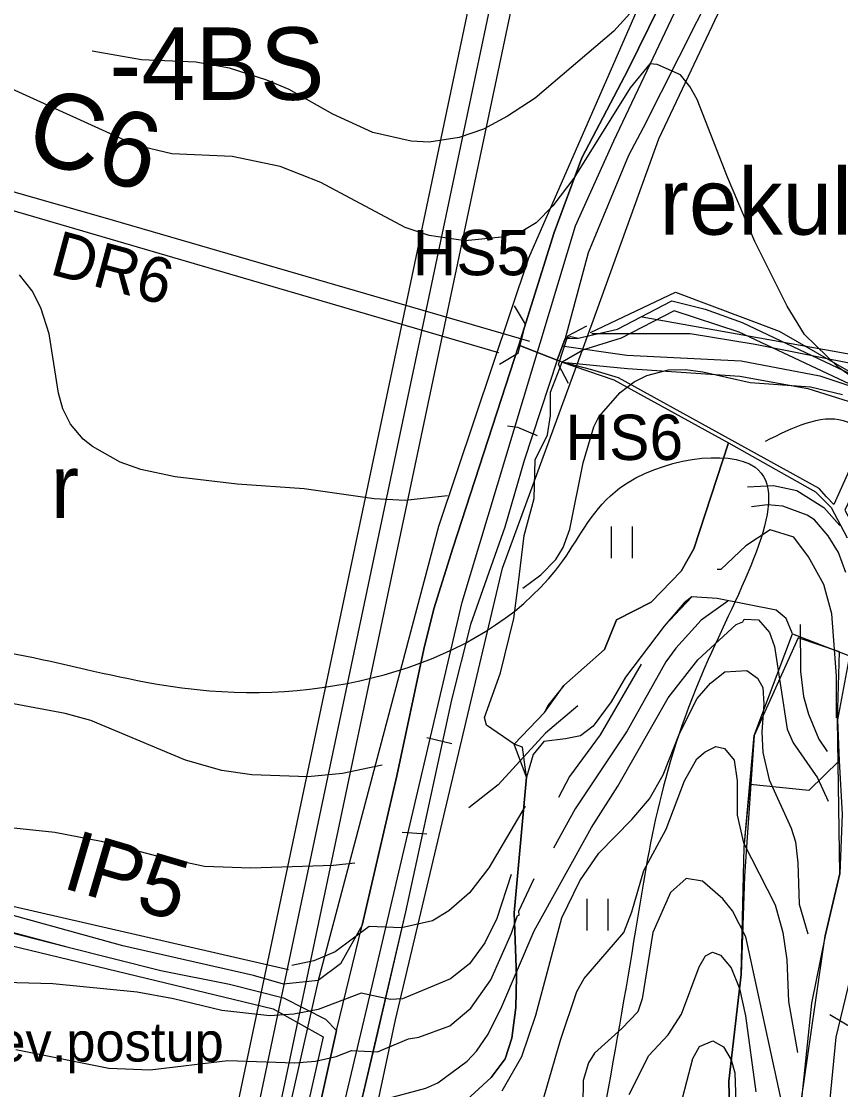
# Model space of a CAD drawing. Extents: x -684583 to -680383, y -1157874 to -1154904.
# Drawn here: x -683067.1 to -682795.6, y -1156658.6 to -1156304.8 of the extents above; entities that cross this region are included whole.
import ezdxf

# ---------------------------------------------------------------- set-up
doc = ezdxf.new("R2010")
doc.units = 0
for name, color, linetype in [('01_DOPRAVA', 7, 'Continuous'), ('01_VRSTEVNICE', 7, 'Continuous'), ('02_KULTURY NÁVRH', 7, 'Continuous'), ('02_KULTURY STAV', 7, 'Continuous'), ('03_PC_NÁVRH', 7, 'Continuous'), ('03_PC_OBJEKTY_NÁVRH', 7, 'Continuous'), ('03_PC_OBJEKTY_STAV', 7, 'Continuous'), ('03_PC_POPIS_NÁVRH', 7, 'Continuous'), ('04_ZPF_OP_ORGAN', 7, 'Continuous'), ('06_BIOGEOGRAFIE', 7, 'Continuous'), ('06_REVITALIZACE', 7, 'Continuous'), ('06_ÚSES_IP', 7, 'Continuous'), ('07_ELEKTRO', 7, 'Continuous'), ('07_OCH_P A POPISY TI', 7, 'Continuous')]:
    doc.layers.add(name, color=color, linetype=linetype)

msp = doc.modelspace()

# ---------------------------------------------------------------- linework, layer by layer
at = {"layer": '01_DOPRAVA'}
msp.add_lwpolyline([(-683054.51, -1157758.92), (-683045.66, -1157702.14), (-683033.32, -1157625.99), (-683033.32, -1157571.3), (-683045.07, -1157508.09), (-683105.62, -1157372.25), (-683148.82, -1157294.04), (-683163.81, -1157254.05), (-683168.81, -1157196.71), (-683165.28, -1157159.67), (-683135.89, -1157075.28), (-683079.46, -1156981.49), (-683035.96, -1156902.98), (-682993.94, -1156817.72), (-682972.78, -1156716.87), (-682952.5, -1156631.31), (-682921.05, -1156497.23), (-682883.43, -1156372.57), (-682870.79, -1156344.34), (-682802.61, -1156200.56), (-682782.62, -1156147.93)], dxfattribs=at)
at = {"layer": '01_VRSTEVNICE'}
for points in [[(-682859.06, -1156295.03), (-682870.76, -1156308.01), (-682896.86, -1156330.26), (-682905.99, -1156336.25), (-682913.98, -1156340.53), (-682921.97, -1156343.24), (-682931.95, -1156344.81), (-682937.94, -1156344.53), (-682950.64, -1156341.67), (-682963.91, -1156335.54), (-682978.31, -1156327.41), (-682985.73, -1156324.27), (-682998.14, -1156320.28), (-683009.27, -1156318.28), (-683027.24, -1156317.57), (-683043.64, -1156314.71)], [(-682788.45, -1156424.98), (-682796.3, -1156419.41), (-682807.57, -1156408.57), (-682813.27, -1156399.16), (-682823.97, -1156377.76), (-682833.1, -1156356.37), (-682843.09, -1156330.69), (-682845.51, -1156326.41), (-682848.65, -1156322.56), (-682856.35, -1156319.14), (-682858.78, -1156318.85), (-682865.34, -1156326.84), (-682884.02, -1156356.79), (-682891.01, -1156365.92), (-682896.43, -1156371.49), (-682900.86, -1156374.2), (-682907.99, -1156376.34), (-682919.97, -1156377.48), (-682931.95, -1156375.77), (-682939.94, -1156373.06), (-682967.9, -1156358.22), (-682981.31, -1156352.94), (-682997.28, -1156349.52), (-683017.25, -1156348.66), (-683029.24, -1156345.81), (-683070.32, -1156327.12)], [(-682925.82, -1156461.92), (-682939.94, -1156463.49), (-682950.21, -1156462.92), (-682973.32, -1156459.64), (-682995.57, -1156458.07), (-683016.11, -1156455.65), (-683027.52, -1156453.22), (-683034.37, -1156450.8), (-683043.5, -1156445.66), (-683046.64, -1156443.24), (-683050.78, -1156438.24), (-683053.34, -1156433.11), (-683054.77, -1156427.97), (-683057.91, -1156408.29), (-683060.62, -1156399.73), (-683063.47, -1156394.03), (-683067.75, -1156388.75)], [(-682900.86, -1156492.5), (-682894.99, -1156488.18), (-682890.01, -1156483.03), (-682887.59, -1156479.04), (-682885.31, -1156473.05), (-682880.89, -1156451.08), (-682877.32, -1156439.1), (-682875.75, -1156435.82), (-682868.62, -1156427.69), (-682864.05, -1156424.26), (-682859.78, -1156422.13), (-682852.64, -1156420.27), (-682846.94, -1156420.13), (-682841.23, -1156420.84), (-682825.54, -1156424.41), (-682805.57, -1156425.83), (-682795.01, -1156428.4)], [(-682905.95, -1156438.78), (-682902.71, -1156439.24), (-682896.15, -1156441.95)], [(-682826.41, -1156458.93), (-682817.87, -1156458.52), (-682810.05, -1156460.17), (-682801.15, -1156465.78), (-682795.87, -1156471.77)], [(-682793.87, -1156487.31), (-682796.3, -1156480.75), (-682799.72, -1156475.19), (-682804.29, -1156469.91), (-682806.71, -1156468.34), (-682814.7, -1156465.35), (-682819.83, -1156464.92), (-682825.11, -1156465.63)], [(-682796.95, -1156535.47), (-682796.95, -1156521.68), (-682798.5, -1156501), (-682801.15, -1156491.31), (-682806.28, -1156482.18), (-682811.13, -1156475.62), (-682818.98, -1156473.19), (-682826.97, -1156478.47), (-682835.24, -1156486.31), (-682836.52, -1156486.31)], [(-682832.96, -1156496.87), (-682841.8, -1156503.15), (-682850.22, -1156512.42), (-682853.5, -1156516.98), (-682866.34, -1156539.81), (-682883.6, -1156565.62), (-682890.73, -1156578.61)], [(-682947.07, -1156661.91), (-682933.09, -1156658.2), (-682929.1, -1156656.35), (-682919.4, -1156649.21), (-682916.26, -1156645.93), (-682912.41, -1156640.23), (-682907.85, -1156631.1), (-682897.15, -1156605.99), (-682878.18, -1156571.76), (-682869.47, -1156558.07), (-682852.79, -1156528.82), (-682842.94, -1156516.27), (-682830.25, -1156504.57), (-682827.96, -1156503.72), (-682827.54, -1156502.86), (-682822.83, -1156503), (-682819.12, -1156507.28), (-682817.55, -1156511.85)], [(-682808.99, -1156504.57), (-682808.85, -1156520.12), (-682807.85, -1156528.4), (-682806.28, -1156534.24), (-682802.86, -1156542.52), (-682800.01, -1156546.65)], [(-682817.55, -1156511.85), (-682813.27, -1156539.24), (-682811.28, -1156543.8), (-682803.28, -1156555.41), (-682799.72, -1156563.06)], [(-682861.73, -1156517.71), (-682875.31, -1156541.17), (-682885.45, -1156554.93), (-682889.13, -1156561.83)], [(-682907.7, -1156659.06), (-682901.28, -1156647.65), (-682896.58, -1156633.95), (-682888.02, -1156601.71), (-682882.03, -1156589.45), (-682875.75, -1156580.32), (-682864.77, -1156569.19), (-682858.92, -1156562.34), (-682854.35, -1156554.36), (-682848.93, -1156540.66), (-682843.09, -1156529.11), (-682838.66, -1156523.97), (-682833.96, -1156520.26), (-682826.68, -1156519.84), (-682823.12, -1156522.4), (-682821.4, -1156525.4), (-682820.98, -1156530.96), (-682821.69, -1156540.09), (-682821.4, -1156546.94), (-682819.26, -1156556.07), (-682811.99, -1156572.04), (-682810.56, -1156576.61), (-682809.71, -1156583.46)], [(-682947.5, -1156551.22), (-682960.62, -1156553.93), (-682972.18, -1156555.07), (-682990.72, -1156554.36), (-683000.71, -1156552.93), (-683012.69, -1156549.51), (-683044.07, -1156536.38), (-683052.63, -1156534.1), (-683069.75, -1156530.82)], [(-682882.62, -1156531.49), (-682893.44, -1156540.52), (-682909.13, -1156557.64), (-682918.83, -1156565.34)], [(-682924.39, -1156544.09), (-682932.67, -1156542.09)], [(-682895.72, -1156667.33), (-682888.45, -1156642.22), (-682883.03, -1156626.11), (-682880.6, -1156621.83), (-682867.48, -1156606.56), (-682864.77, -1156599.72), (-682860.77, -1156586.02), (-682853.36, -1156572.33), (-682847.36, -1156556.35), (-682843.23, -1156549.08), (-682840.52, -1156546.8), (-682836.95, -1156544.94), (-682834.1, -1156545.65), (-682830.82, -1156549.51), (-682829.82, -1156556.35), (-682829.82, -1156567.76), (-682827.82, -1156576.89), (-682817.27, -1156597.43), (-682814.7, -1156606.56), (-682813.42, -1156615.69), (-682812.84, -1156629.39), (-682809.85, -1156646.36)], [(-682900.08, -1156564.75), (-682912.12, -1156585.17), (-682918.54, -1156593.44), (-682925.39, -1156599.43), (-682930.81, -1156602.71), (-682941.08, -1156604.99), (-682951.78, -1156604.57), (-682963.05, -1156612.98), (-682970.18, -1156615.98), (-682977.46, -1156617.55)], [(-683091.71, -1156569.62), (-683056.05, -1156573.33), (-683040.65, -1156576.32), (-683021.82, -1156581.32), (-683006.41, -1156584.6), (-682991.01, -1156585.17), (-682963.62, -1156584.31), (-682956.63, -1156583.46)], [(-682932.67, -1156574.04), (-682940.94, -1156573.47)], [(-682809.71, -1156583.46), (-682809.28, -1156597.15), (-682806.43, -1156606.99)], [(-682904.77, -1156587.35), (-682909.56, -1156602), (-682913.55, -1156609.99), (-682918.54, -1156616.98), (-682924.82, -1156621.97), (-682940.8, -1156628.53), (-682944.79, -1156628.82), (-682954.49, -1156626.68), (-682968.75, -1156632.1), (-682976.74, -1156633.67), (-682984.73, -1156634.24), (-683000.71, -1156632.38), (-683016.68, -1156628.53), (-683028.67, -1156626.39), (-683056.62, -1156623.54), (-683072.6, -1156623.11)], [(-683068.89, -1156645.36), (-683038.08, -1156651.5), (-683024.39, -1156652.07), (-682998.71, -1156648.93), (-682976.46, -1156649.78), (-682969.61, -1156649.21), (-682962.76, -1156647.65), (-682957.63, -1156645.65), (-682949.07, -1156646.08), (-682938.8, -1156641.8), (-682935.38, -1156641.23), (-682925.11, -1156637.52), (-682918.12, -1156631.67), (-682911.55, -1156622.25), (-682904.71, -1156606.85), (-682902.71, -1156601), (-682902.14, -1156600.86), (-682902.28, -1156599.5), (-682897.15, -1156588.73)], [(-682814.94, -1156663.44), (-682826.97, -1156607.99), (-682831.39, -1156599.43), (-682834.67, -1156595.44), (-682841.37, -1156589.59), (-682846.79, -1156588.73), (-682851.93, -1156593.3), (-682857.78, -1156606.56), (-682861.34, -1156628.53), (-682862.77, -1156632.81), (-682868.05, -1156638.37), (-682877.18, -1156646.5), (-682879.17, -1156649.78), (-682880.89, -1156655.63), (-682881.17, -1156671.89)], [(-682865.62, -1156660.2), (-682859.2, -1156647.36), (-682852.79, -1156640.51), (-682848.36, -1156633.67), (-682842.51, -1156617.98), (-682840.38, -1156614.27), (-682838.09, -1156613.13), (-682835.38, -1156614.12), (-682831.82, -1156618.26), (-682829.11, -1156625.11), (-682827.11, -1156634.24), (-682823.69, -1156659.34)], [(-682799.14, -1156633.78), (-682786.88, -1156641.08), (-682763.92, -1156656.63), (-682743.38, -1156668.04), (-682727.4, -1156674.6), (-682711.42, -1156679.74), (-682687.46, -1156686.02), (-682675.05, -1156691.01), (-682666.35, -1156697.29), (-682664.21, -1156699.57), (-682660.07, -1156706.41), (-682658.36, -1156710.98), (-682656.65, -1156720.11), (-682657.51, -1156744.93), (-682655.51, -1156761.9), (-682655.51, -1156767.47), (-682657.51, -1156777.74), (-682660.5, -1156786.3), (-682661.93, -1156792.86), (-682662.88, -1156799.77), (-682662.11, -1156829.16)], [(-682849.93, -1156669.04), (-682844.51, -1156648.36), (-682842.37, -1156644.36), (-682837.95, -1156642.51), (-682834.38, -1156644.51), (-682831.82, -1156648.79), (-682830.68, -1156653.07), (-682830.25, -1156665.9)]]:
    msp.add_lwpolyline(points, dxfattribs=at)
at = {"layer": '02_KULTURY NÁVRH'}
for points in [[(-682887.91, -1156417.72), (-682866.23, -1156419.79), (-682828.98, -1156422.33), (-682806.49, -1156426.37), (-682783.26, -1156433.67), (-682787.89, -1156443.08), (-682788.73, -1156444.69), (-682797.87, -1156464.81), (-682800.21, -1156462.31), (-682802.73, -1156459.5), (-682869.24, -1156422.91), (-682878.07, -1156420.23)], [(-682811.55, -1156507.67), (-682792.62, -1156514.96), (-682796.58, -1156536.16), (-682796.03, -1156549.68), (-682806.13, -1156559.58), (-682825.6, -1156557.59), (-682824.2, -1156541.34)]]:
    msp.add_lwpolyline(points, close=True, dxfattribs=at)
at = {"layer": '02_KULTURY STAV'}
for points in [[(-682848.78, -1156285.62), (-682866.04, -1156320.76), (-682881.3, -1156350.03), (-682890.5, -1156374.69), (-682902.2, -1156412.07), (-682924.11, -1156479.25), (-682930.39, -1156499.36), (-682933.67, -1156512.75), (-682942.64, -1156554.75), (-682954.15, -1156604.14), (-682961.33, -1156617), (-682968.71, -1156622.54), (-682980.17, -1156623.7), (-682990.2, -1156620.86), (-683033.47, -1156611), (-683082.29, -1156597.58)], [(-682837.34, -1156293.13), (-682860.97, -1156340.11), (-682865.88, -1156349.21), (-682879.26, -1156381.53), (-682886.9, -1156409.8), (-682889.47, -1156417.03), (-682902.2, -1156412.07), (-682890.5, -1156374.69), (-682881.3, -1156350.03), (-682866.04, -1156320.76), (-682848.78, -1156285.62)], [(-682837.34, -1156293.13), (-682860.97, -1156340.11), (-682865.88, -1156349.21), (-682879.26, -1156381.53), (-682886.9, -1156409.8), (-682882.56, -1156409.71), (-682869.55, -1156406.81), (-682851.47, -1156397.34), (-682840.47, -1156400.15), (-682828.26, -1156404.5), (-682752.66, -1156440.28), (-682665.48, -1156481.67), (-682644.77, -1156490.96), (-682634.17, -1156493.17), (-682633.78, -1156490.12), (-682629.07, -1156473.67), (-682624.47, -1156460.14), (-682619.39, -1156445.85), (-682614.21, -1156430.78), (-682608.85, -1156415.21), (-682596.72, -1156380.07), (-682557.32, -1156288.22)], [(-682754.25, -1156442.99), (-682829.25, -1156407.8), (-682850.76, -1156400.72), (-682868.28, -1156409.71), (-682880.84, -1156413.58), (-682887.91, -1156417.72), (-682870.7, -1156423.51), (-682832.78, -1156444.43), (-682803.95, -1156460.65), (-682798.7, -1156465.79), (-682793.43, -1156475.86)], [(-682922.2, -1156664.52), (-682911.39, -1156654.62), (-682906.77, -1156648.44), (-682904.56, -1156641.63), (-682903.21, -1156631.38), (-682903.03, -1156621.21), (-682903.76, -1156600.02), (-682899.73, -1156555.19), (-682901.04, -1156545.15), (-682903.77, -1156544.17), (-682912.98, -1156537.95), (-682913.56, -1156535.35), (-682908.35, -1156520.61), (-682903.84, -1156502.54), (-682902.5, -1156491.58), (-682900.5, -1156475.1), (-682897.2, -1156462.81), (-682896.82, -1156450.01), (-682892.68, -1156441.75), (-682891.73, -1156435.33), (-682891.71, -1156427.67), (-682887.91, -1156417.72), (-682889.47, -1156417.03), (-682900.44, -1156450.21), (-682906.88, -1156472.32), (-682912.15, -1156487.33), (-682918.22, -1156504.6), (-682924.52, -1156529.58), (-682939.75, -1156599.76), (-682962.33, -1156695.9)], [(-682832.12, -1156679.28), (-682832.61, -1156655.83), (-682828.57, -1156620.45), (-682827.59, -1156578.27), (-682825.6, -1156557.59), (-682824.2, -1156541.34), (-682811.55, -1156507.67), (-682813.64, -1156502.61), (-682816.94, -1156499.88), (-682836.55, -1156495.99), (-682844.88, -1156495.39), (-682847.39, -1156497.44), (-682854.11, -1156505.13), (-682866.83, -1156522.06), (-682871.68, -1156530.15), (-682877.57, -1156538.3), (-682881.79, -1156541.44), (-682886.74, -1156542.41), (-682893.92, -1156543.32), (-682897.52, -1156547.62), (-682899.73, -1156555.19), (-682903.77, -1156544.17), (-682893.76, -1156533.76), (-682887.33, -1156524.78), (-682873.81, -1156512.91), (-682869.89, -1156502.98), (-682858.35, -1156497.14), (-682848.45, -1156486.87), (-682844.25, -1156479.54), (-682832.78, -1156444.43), (-682803.95, -1156460.65), (-682798.7, -1156465.79), (-682793.43, -1156475.86)], [(-682871.68, -1156472.16), (-682871.68, -1156482.66)], [(-682864.68, -1156472.16), (-682864.68, -1156482.66)], [(-682832.12, -1156679.28), (-682832.61, -1156655.83), (-682828.57, -1156620.45), (-682827.59, -1156578.27), (-682824.2, -1156541.34), (-682811.55, -1156507.67), (-682813.64, -1156502.61), (-682816.94, -1156499.88), (-682836.55, -1156495.99), (-682844.88, -1156495.39), (-682854.11, -1156505.13), (-682866.83, -1156522.06), (-682871.68, -1156530.15), (-682877.57, -1156538.3), (-682881.79, -1156541.44), (-682886.74, -1156542.41), (-682893.92, -1156543.32), (-682897.52, -1156547.62), (-682899.73, -1156555.19), (-682903.76, -1156600.02), (-682903.03, -1156621.21), (-682903.21, -1156631.38), (-682904.56, -1156641.63), (-682906.77, -1156648.44), (-682911.39, -1156654.62), (-682922.2, -1156664.52)], [(-682792.62, -1156514.96), (-682796.58, -1156536.16), (-682796.03, -1156549.68), (-682795.1, -1156567.41), (-682795.87, -1156587.1), (-682800.74, -1156607.7), (-682805.25, -1156630.03), (-682808.53, -1156661.75), (-682809.42, -1156675.8), (-682811.51, -1156694.23), (-682814.12, -1156742.41), (-682814.76, -1156765.27), (-682825.52, -1156817.11), (-682826.23, -1156835.78), (-682833.65, -1156897.15), (-682841.03, -1156977.03), (-682844.53, -1157035.81), (-682845.68, -1157065.25), (-682844.82, -1157086.77), (-682850.09, -1157090.88), (-682805.97, -1157127.99), (-682750, -1157164.87)], [(-682792.62, -1156514.96), (-682796.58, -1156536.16), (-682796.03, -1156549.68), (-682795.1, -1156567.41), (-682795.87, -1156587.1), (-682800.74, -1156607.7), (-682805.25, -1156630.03), (-682808.53, -1156661.75)], [(-682879.74, -1156595.4), (-682879.74, -1156605.9)], [(-682872.74, -1156595.4), (-682872.74, -1156605.9)]]:
    msp.add_lwpolyline(points, dxfattribs=at)
for points in [[(-682889.47, -1156417.03), (-682886.9, -1156409.8), (-682885.02, -1156409.17), (-682882.56, -1156409.71), (-682869.55, -1156406.81), (-682851.47, -1156397.34), (-682840.47, -1156400.15), (-682828.26, -1156404.5), (-682752.66, -1156440.28), (-682665.48, -1156481.67), (-682644.77, -1156490.96), (-682635.67, -1156493), (-682634.17, -1156493.17), (-682635.01, -1156500.02), (-682667.07, -1156484.3), (-682754.25, -1156442.99), (-682829.25, -1156407.8), (-682850.76, -1156400.72), (-682868.28, -1156409.71), (-682880.84, -1156413.58), (-682887.91, -1156417.72)], [(-682976.5, -1156701.12), (-682962.69, -1156639.04), (-682954.15, -1156604.14), (-682942.64, -1156554.75), (-682933.67, -1156512.75), (-682930.39, -1156499.36), (-682924.11, -1156479.25), (-682902.2, -1156412.07), (-682889.47, -1156417.03), (-682900.44, -1156450.21), (-682906.88, -1156472.32), (-682918.22, -1156504.6), (-682924.52, -1156529.58), (-682939.75, -1156599.76), (-682949.64, -1156642.25), (-682962.33, -1156695.9)], [(-682887.91, -1156417.72), (-682870.7, -1156423.51), (-682832.78, -1156444.43), (-682844.25, -1156479.54), (-682848.45, -1156486.87), (-682858.35, -1156497.14), (-682869.89, -1156502.98), (-682873.81, -1156512.91), (-682887.33, -1156524.78), (-682892.59, -1156531.36), (-682893.76, -1156533.76), (-682903.77, -1156544.17), (-682912.98, -1156537.95), (-682913.56, -1156535.35), (-682908.35, -1156520.61), (-682903.84, -1156502.54), (-682902.5, -1156491.58), (-682900.5, -1156475.1), (-682897.2, -1156462.81), (-682896.82, -1156450.01), (-682892.68, -1156441.75), (-682891.73, -1156435.33), (-682891.71, -1156427.67)], [(-683092.79, -1156585.88), (-683084.93, -1156572.48), (-683093.79, -1156577.44), (-683104.92, -1156586.73), (-683111.36, -1156596.26), (-683088.76, -1156601.48), (-683052.03, -1156611.32), (-683020.92, -1156619.13), (-682998.1, -1156623.73), (-682980.21, -1156628.28), (-682966.28, -1156635.31), (-682962.69, -1156639.04), (-682954.15, -1156604.14), (-682961.33, -1156617), (-682968.71, -1156622.54), (-682980.17, -1156623.7), (-682990.2, -1156620.86), (-683033.47, -1156611), (-683082.29, -1156597.58), (-683095.01, -1156593.22)], [(-683111.36, -1156596.26), (-683052.03, -1156611.32), (-683020.92, -1156619.13), (-682998.1, -1156623.73), (-682980.21, -1156628.28), (-682966.28, -1156635.31), (-682962.69, -1156639.04), (-682976.5, -1156701.12), (-683073.72, -1156680.66), (-683140.88, -1156658.35), (-683138.49, -1156642.27), (-683137.49, -1156635.26), (-683133.3, -1156627.22), (-683127.66, -1156620.6)]]:
    msp.add_lwpolyline(points, close=True, dxfattribs=at)
at = {"layer": '03_PC_NÁVRH'}
for points in [[(-682898.58, -1156410.84), (-683039.99, -1156369.8), (-683186.84, -1156328.1), (-683202.59, -1156325.5), (-683221.21, -1156329.82)], [(-682887.94, -1156412.25), (-682866.49, -1156415.4), (-682828.6, -1156417.26), (-682802.44, -1156422.27), (-682780.99, -1156429.42), (-682635.3, -1156496.52)]]:
    msp.add_lwpolyline(points, dxfattribs=at)
at = {"layer": '03_PC_OBJEKTY_NÁVRH'}
for points in [[(-682908.91, -1156414.57), (-683182.86, -1156334.61), (-683204.55, -1156331.09), (-683218.23, -1156335.4)], [(-682878.05, -1156408.2), (-682845.44, -1156408.2), (-682823.88, -1156411.7), (-682788.84, -1156418.72), (-682758.65, -1156431.66), (-682640.05, -1156486.4)]]:
    msp.add_lwpolyline(points, dxfattribs=at)
at = {"layer": '03_PC_OBJEKTY_STAV'}
for points in [[(-682903.82, -1156399.01), (-682900.17, -1156405.07), (-682902.57, -1156414.77), (-682908.63, -1156418.42)], [(-682885.81, -1156424.75), (-682889.06, -1156418.46), (-682886.02, -1156408.94), (-682879.74, -1156405.69)]]:
    msp.add_lwpolyline(points, dxfattribs=at)
at = {"layer": '04_ZPF_OP_ORGAN'}
for points in [[(-682779.67, -1156436.1), (-682794.2, -1156466.69), (-682788.61, -1156477.13), (-682784.14, -1156488.69), (-682785.65, -1156500.47), (-682788.37, -1156536.68), (-682784.46, -1156588.73), (-682797.19, -1156641.23), (-682810.23, -1156775.49), (-682822.53, -1156859.77), (-682834.09, -1156965.69), (-682838.67, -1157072.57), (-682735.79, -1157152.27), (-682675.08, -1157204.91), (-682675.48, -1157169.72), (-682684.88, -1157129.04), (-682735.36, -1157001.81), (-682708.95, -1156906.13), (-682698.09, -1156909.32), (-682682.43, -1156889.14), (-682649.29, -1156744.14), (-682652.93, -1156622.47), (-682648.88, -1156555.77), (-682641, -1156504.41)], [(-683109.63, -1156601.48), (-682983.62, -1156631.85), (-682967.02, -1156641.18), (-682979.45, -1156695.86), (-683071.68, -1156677.56), (-683136.35, -1156655.1), (-683133.94, -1156635.23)]]:
    msp.add_lwpolyline(points, close=True, dxfattribs=at)
at = {"layer": '06_BIOGEOGRAFIE'}
for points in [[(-682624.87, -1154935.44), (-682669.05, -1155140.04), (-682739.65, -1155253.72), (-682834.36, -1155382.91), (-682941.12, -1155661.96), (-683008.28, -1155760.14), (-683056.49, -1155810.09), (-683084.04, -1155808.37), (-683154.45, -1155886.49), (-683231.94, -1156062.19), (-683280.08, -1156211.64), (-683362.74, -1156430.39), (-683497.05, -1156731.83), (-683541.82, -1156781.78), (-683638.25, -1156792.12), (-683701.96, -1156768), (-683817.33, -1156693.94)], [(-682820.52, -1156443.86), (-682794.69, -1156436.97), (-682777.47, -1156454.19), (-682792.96, -1156667.78), (-682801.57, -1156726.35), (-682792.96, -1156755.63), (-682811.91, -1156802.14), (-682839.46, -1156886.54), (-682887.67, -1157000.23), (-682920.39, -1157038.12)], [(-683099.47, -1156889.99), (-683108.08, -1156852.09), (-683133.91, -1156841.76), (-683133.91, -1156814.2), (-683132.19, -1156784.91), (-683147.69, -1156747.02), (-683189.01, -1156748.74), (-683242.39, -1156712.57), (-683235.51, -1156631.61), (-683171.79, -1156531.71), (-683097.75, -1156511.04), (-683004.76, -1156526.54), (-682887.67, -1156483.48), (-682868.73, -1156459.36), (-682823.96, -1156452.47), (-682839.46, -1156516.2), (-682863.56, -1156605.77), (-682887.67, -1156736.68), (-682923.83, -1156891.71), (-682934.16, -1156915.82), (-682965.16, -1156929.6), (-683004.76, -1156926.16)]]:
    msp.add_spline(points, degree=3, dxfattribs=at)
at = {"layer": '06_REVITALIZACE'}
msp.add_lwpolyline([(-682878.47, -1156407.84), (-682850.28, -1156394.53), (-682815.93, -1156407.44), (-682791.31, -1156421.54)], dxfattribs=at)
at = {"layer": '06_ÚSES_IP'}
for points in [[(-682530.18, -1155187.74), (-682556.31, -1155287.32), (-682580.65, -1155417.4), (-682596.62, -1155505.37), (-682619.02, -1155596.96), (-682637.3, -1155662.36), (-682672.55, -1155772.07), (-682712.43, -1155905.02), (-682772.45, -1156078.06), (-682846.1, -1156262.2), (-682899.06, -1156383.28), (-682928.82, -1156472.07), (-682968.71, -1156622.54), (-683017.6, -1156838.34)], [(-683045.5, -1156945.1), (-682993.87, -1156850.83), (-682970.35, -1156763.63), (-682943.14, -1156635.49), (-682907.69, -1156485.87), (-682877.43, -1156403.71), (-682855.81, -1156343.74), (-682797.01, -1156219.49), (-682773.09, -1156158.67), (-682722.07, -1156008.47), (-682663.84, -1155833.77), (-682598.99, -1155629.09), (-682554.6, -1155429.31), (-682533.56, -1155299)], [(-682861.35, -1156402.68), (-682780.44, -1156417.1), (-682666.3, -1156469.98), (-682637.06, -1156481.6)], [(-682808.53, -1156661.75), (-682800.74, -1156607.7), (-682795.87, -1156587.1), (-682796.58, -1156536.16), (-682796, -1156513.66), (-682809.7, -1156508.95), (-682824.2, -1156541.34), (-682827.42, -1156587.94), (-682828.57, -1156620.45), (-682832.61, -1156655.83), (-682832.12, -1156679.28)], [(-683110.87, -1156588.52), (-682978.56, -1156618.79)]]:
    msp.add_lwpolyline(points, dxfattribs=at)
at = {"layer": '07_ELEKTRO'}
msp.add_lwpolyline([(-683353.35, -1157770.3), (-683109.07, -1157109.08), (-683073.5, -1157019.42), (-683054.68, -1156978.22), (-683011.49, -1156911.63), (-683020.57, -1156816.29), (-682818.44, -1155857.57), (-682314.17, -1155533.82)], dxfattribs=at)
msp.add_lwpolyline([(-683353.35, -1157770.3), (-683109.07, -1157109.08), (-683073.5, -1157019.42), (-683054.68, -1156978.22), (-683011.49, -1156911.63), (-683020.57, -1156816.29), (-682818.44, -1155857.57), (-682314.17, -1155533.82)], dxfattribs=at)
at = {"layer": '07_OCH_P A POPISY TI'}
for p, q in [((-682826.85, -1155863.53), (-683027.64, -1156815.89)), ((-683013.5, -1156816.69), (-682812.19, -1155861.88))]:
    msp.add_line(p, q, dxfattribs=at)

# ---------------------------------------------------------------- texts
at = {"layer": '02_KULTURY STAV'}
msp.add_text('r', height=21, dxfattribs=at).set_placement((-683057.36, -1156469.29))
at = {"layer": '03_PC_OBJEKTY_NÁVRH'}
msp.add_text('DR6', height=15, rotation=344.8954, dxfattribs=at).set_placement((-683058.1, -1156388.44))
at = {"layer": '03_PC_OBJEKTY_STAV'}
for s, p in [('HS5', (-682937.42, -1156388.91)), ('HS6', (-682886.79, -1156450.09))]:
    msp.add_text(s, height=15, dxfattribs=at).set_placement(p)
at = {"layer": '03_PC_POPIS_NÁVRH'}
msp.add_text('C6', height=25, rotation=344.1463, dxfattribs=at).set_placement((-683066.76, -1156349.9))
at = {"layer": '04_ZPF_OP_ORGAN'}
msp.add_text('PEO1,osev.postup', height=13, dxfattribs=at).set_placement((-683144.96, -1156649.32))
at = {"layer": '06_BIOGEOGRAFIE'}
msp.add_text('-4BS', height=24, dxfattribs=at).set_placement((-683037.98, -1156330.81))
at = {"layer": '06_REVITALIZACE'}
msp.add_text('rekult.cesty', height=22, dxfattribs=at).set_placement((-682855.64, -1156375.46))
at = {"layer": '06_ÚSES_IP'}
msp.add_text('IP5', height=20, rotation=343.6414, dxfattribs=at).set_placement((-683054.06, -1156591.67))

doc.saveas('drawing.dxf')
